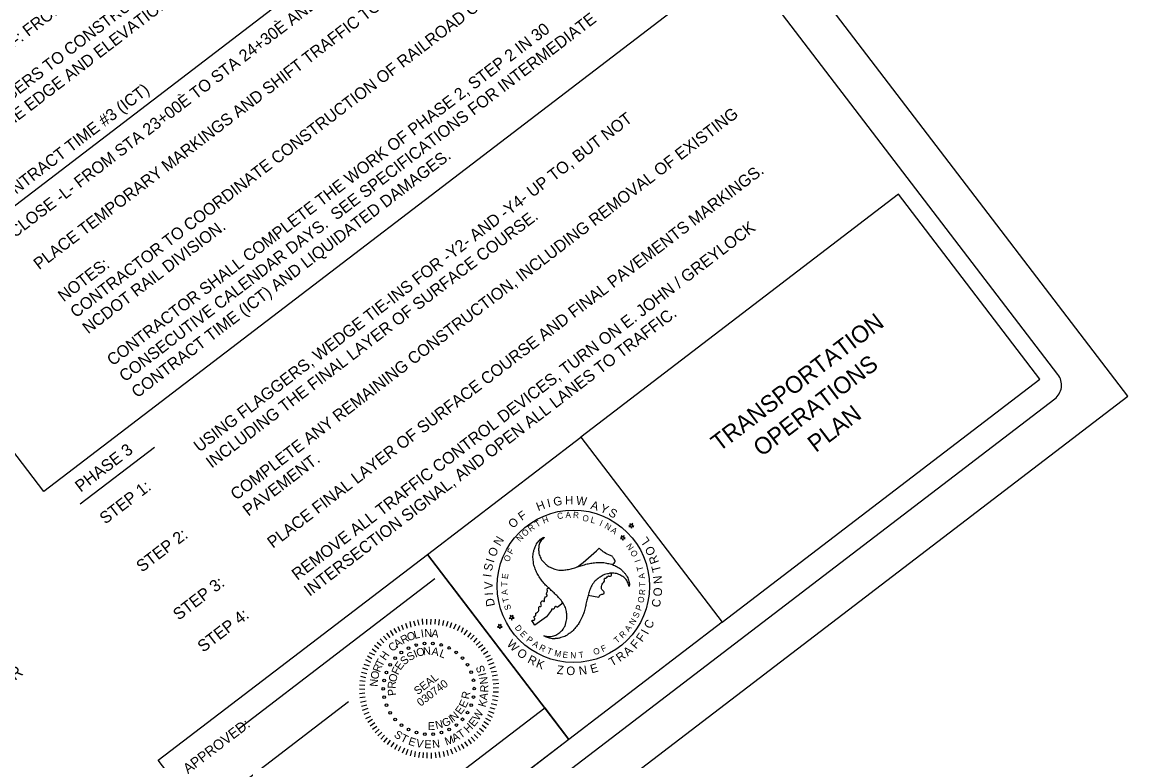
# Model space of a CAD drawing. Extents: x -606 to 2396, y -305 to 3662.
# Drawn here: x 1352 to 2005, y 861 to 1297 of the extents above; entities that cross this region are included whole.
import ezdxf

# ---------------------------------------------------------------- set-up
doc = ezdxf.new("R2010")
doc.units = 0
for name, color, linetype in [('DEV BORDER CELL', 7, 'Continuous'), ('DEV DOT SWIRL SEAL CELL', 7, 'Continuous'), ('Old_Level_9', 7, 'Continuous'), ('Sheet Plot Border Outside CELL', 7, 'Continuous'), ('Sheet Sticker Exception Certification CELL', 7, 'Continuous'), ('Text', 7, 'Continuous')]:
    doc.layers.add(name, color=color, linetype=linetype)

msp = doc.modelspace()

# ---------------------------------------------------------------- linework, layer by layer
at = {"layer": 'DEV BORDER CELL'}
for p, q in [((1963.25, 1088.61), (1337.94, 1906.36)), ((786.1, 175.54), (1961.32, 1074.19)), ((1479.25, 879.26), (1595.5, 968.15)), ((1605.31, 963.79), (1674.56, 873.24)), ((1481.07, 847.06), (1544.45, 895.53))]:
    msp.add_line(p, q, dxfattribs=at)
for points in [[(1869.07, 1195.06), (1681.6, 1051.71), (1765.12, 942.48), (1952.59, 1085.83)], [(1591.04, 982.46), (1681.6, 1051.71), (1765.12, 942.48), (1674.56, 873.23)], [(1432.13, 860.95), (1591.04, 982.46), (1674.56, 873.23), (1515.66, 751.72)]]:
    msp.add_lwpolyline(points, close=True, dxfattribs=at)
msp.add_arc((1955.08, 1082.36), 10.29, 307.40396, 37.40402, dxfattribs=at)
at = {"layer": 'DEV DOT SWIRL SEAL CELL'}
for p, q in [((1710.83, 999.54), (1709.97, 998.88)), ((1709.97, 998.88), (1711.06, 998.91)), ((1711.37, 999.96), (1710.48, 1000.53)), ((1710.48, 1000.53), (1710.83, 999.54)), ((1711.06, 998.91), (1711.44, 997.89)), ((1712.24, 1000.62), (1711.37, 999.96)), ((1711.44, 997.89), (1711.72, 998.91)), ((1711.72, 998.91), (1712.81, 998.94)), ((1711.92, 999.57), (1712.24, 1000.62)), ((1712.81, 998.94), (1711.92, 999.57)), ((1705.86, 992.42), (1705, 991.76)), ((1706.4, 992.83), (1705.51, 993.41)), ((1705.51, 993.41), (1705.86, 992.42)), ((1707.26, 993.49), (1706.4, 992.83)), ((1706.95, 992.44), (1707.26, 993.49)), ((1707.84, 991.81), (1706.95, 992.44)), ((1705, 991.76), (1706.09, 991.78)), ((1706.09, 991.78), (1706.47, 990.76)), ((1706.47, 990.76), (1706.75, 991.78)), ((1706.75, 991.78), (1707.84, 991.81)), ((1667.64, 951.35), (1671.01, 953.88)), ((1685.95, 958.28), (1692.21, 957.18)), ((1664.36, 949.55), (1661.4, 945.51)), ((1633.29, 940.07), (1632.43, 939.41)), ((1633.83, 940.48), (1632.93, 941.06)), ((1632.93, 941.06), (1633.29, 940.07)), ((1634.69, 941.14), (1633.83, 940.48)), ((1634.38, 940.1), (1634.69, 941.14)), ((1634.38, 940.1), (1634.69, 941.14)), ((1635.27, 939.46), (1634.38, 940.1)), ((1635.27, 939.46), (1634.38, 940.1)), ((1640.19, 945.33), (1639.33, 944.67)), ((1639.33, 944.67), (1640.42, 944.7)), ((1640.73, 945.75), (1639.84, 946.32)), ((1639.84, 946.32), (1640.19, 945.33)), ((1640.42, 944.7), (1640.8, 943.68)), ((1641.59, 946.4), (1640.73, 945.75)), ((1640.8, 943.68), (1641.08, 944.7)), ((1641.08, 944.7), (1642.17, 944.72)), ((1641.28, 945.36), (1641.59, 946.4)), ((1642.17, 944.72), (1641.28, 945.36)), ((1654.54, 940.66), (1653, 942.82)), ((1661.4, 945.51), (1654.54, 940.66)), ((1632.43, 939.41), (1633.52, 939.44)), ((1633.52, 939.44), (1633.9, 938.41)), ((1633.9, 938.41), (1634.18, 939.44)), ((1634.18, 939.44), (1635.27, 939.46)), ((1634.18, 939.44), (1635.27, 939.46))]:
    msp.add_line(p, q, dxfattribs=at)
for start, end in [(308.60748, 312.72752), (303.08246, 303.3802)]:
    msp.add_arc((1534.24, 1157.31), 233.19, start, end, dxfattribs=at)
for points in [[(1659.8, 934.46), (1662.41, 933.93), (1664.98, 934.14), (1667.36, 935.14), (1669.69, 936.73), (1671.57, 939), (1672.5, 940.93), (1672.74, 941.93), (1673.18, 943.65), (1673.32, 945.11), (1673.21, 948), (1672.54, 951), (1671.02, 953.86), (1670.88, 954.09), (1669.03, 956.46), (1666.87, 958.63), (1664.75, 960.69), (1662.48, 962.77), (1660.28, 964.87), (1658.45, 967.16), (1656.56, 969.94), (1655.2, 972.52), (1654.16, 975.43), (1653.71, 976.85), (1653.58, 978.17), (1653.36, 981.34), (1653.86, 984.43), (1654.37, 986.24), (1655.04, 987.7), (1655.16, 987.96), (1656.86, 990.41), (1659.01, 992.19), (1659.91, 992.57)], [(1659.92, 992.68), (1659.91, 992.57), (1658.15, 990.62), (1657.03, 988.24), (1656.71, 985.7), (1656.92, 982.92), (1657.96, 980.13), (1659.14, 978.37), (1659.91, 977.67), (1661.18, 976.41), (1662.35, 975.55), (1664.93, 974.24), (1667.85, 973.3), (1671.11, 973.19), (1671.38, 973.19), (1674.32, 973.58), (1677.32, 974.39), (1680.15, 975.2), (1683.07, 976.12), (1686.01, 976.95), (1688.91, 977.4), (1692.26, 977.67), (1695.15, 977.55), (1698.2, 977.01), (1699.67, 976.68), (1700.87, 976.12), (1703.74, 974.76), (1706.15, 972.75), (1707.49, 971.4), (1708.42, 970.09), (1708.59, 969.88), (1709.83, 967.15), (1710.28, 964.39), (1710.18, 963.46)], [(1700.13, 976.48), (1701.91, 978.23), (1701.01, 980), (1700.04, 981.32), (1698.08, 982.2), (1694.76, 984.04), (1692.46, 986.02)], [(1710.18, 963.46), (1709.36, 965.94), (1707.89, 968.09), (1705.82, 969.65), (1703.3, 970.87), (1700.39, 971.35), (1698.27, 971.21), (1697.27, 970.89), (1695.56, 970.47), (1694.2, 969.82), (1691.79, 968.29), (1689.5, 966.2), (1687.79, 963.44), (1687.66, 963.21), (1686.55, 960.43), (1685.73, 957.47), (1684.98, 954.6), (1684.34, 951.61), (1683.61, 948.62), (1682.54, 945.91), (1681.08, 942.87), (1679.53, 940.43), (1677.55, 938.07), (1676.52, 936.95), (1675.44, 936.19), (1672.85, 934.41), (1669.89, 933.29), (1668.08, 932.83), (1666.46, 932.7), (1666.18, 932.66), (1663.21, 932.92), (1660.61, 933.9), (1659.8, 934.46)], [(1692.21, 957.18), (1693.24, 958.62), (1694.69, 959.05), (1695.3, 959.37), (1695.49, 960.05), (1694.07, 961.63), (1693.85, 962.71), (1694.64, 965.45), (1695.57, 966.55), (1695.61, 968.22), (1695.97, 968.45), (1696.7, 968.56), (1697.68, 969.66), (1699.16, 969.62), (1699.67, 970.08), (1699.46, 971.25)], [(1653, 942.82), (1652.78, 942.97), (1652.97, 943.47), (1654.26, 943.82), (1654.43, 944.62), (1654.08, 945.03), (1654.16, 945.77), (1654.93, 946.15), (1654.96, 947.38), (1655.4, 947.96), (1656.59, 948.87), (1656.92, 951.37), (1657.44, 951.9), (1657.88, 951.64), (1658.29, 951.85), (1658.03, 953.5), (1658.07, 953.77), (1658.8, 955.05), (1659.26, 955.05), (1659.75, 954.6), (1659.97, 954.63), (1660.14, 955.15), (1660.16, 956.16), (1660.69, 957.32), (1661.83, 957.97), (1661.36, 958.96), (1661.95, 960.69), (1661.82, 961.38), (1661.51, 961.92)], [(1667.64, 951.35), (1666.98, 951.66), (1666.32, 951.4), (1665.87, 950.46), (1665.31, 950.06), (1664.36, 950.05), (1664.36, 949.55)]]:
    msp.add_spline(points, degree=3, dxfattribs=at)
at = {"layer": 'Old_Level_9'}
for p, q in [((1575.7, 940.95), (1576.83, 938.03)), ((1578.05, 941.8), (1579.17, 938.88)), ((1580.59, 942.79), (1581.22, 939.5)), ((1582.88, 943.29), (1583.73, 940.32)), ((1585.28, 943.86), (1585.91, 940.57)), ((1587.92, 944.31), (1588.1, 940.99)), ((1590.5, 944.24), (1590.53, 941.11)), ((1593, 944.26), (1592.93, 941.06)), ((1595.57, 944.18), (1595.35, 941.18)), ((1597.95, 943.96), (1597.61, 940.7)), ((1600.56, 943.43), (1599.88, 940.4)), ((1603.06, 942.83), (1602.04, 939.84)), ((1605.37, 942.08), (1604.35, 939.09)), ((1607.75, 941.22), (1606.55, 938.26)), ((1610.11, 940.19), (1608.56, 937.28)), ((1565.07, 934.07), (1567.19, 931.92)), ((1567, 935.87), (1568.97, 933.29)), ((1569.09, 937.46), (1570.76, 934.65)), ((1571.2, 938.61), (1572.82, 936.07)), ((1573.51, 939.9), (1574.84, 937.14)), ((1612.2, 939.11), (1610.92, 936.25)), ((1614.59, 937.64), (1612.61, 934.87)), ((1616.62, 936.21), (1614.67, 933.61)), ((1618.56, 934.7), (1616.46, 932.3)), ((1559.82, 928.8), (1562.41, 926.85)), ((1561.4, 930.64), (1563.72, 928.64)), ((1563.26, 932.53), (1565.28, 930.3)), ((1620.3, 933.04), (1618.3, 930.72)), ((1622.1, 931.11), (1619.74, 928.83)), ((1623.79, 929.1), (1621.31, 927.2)), ((1625.23, 927.21), (1622.75, 925.31)), ((1555.67, 922.49), (1558.31, 920.89)), ((1556.76, 924.57), (1559.77, 923.1)), ((1558.38, 926.76), (1560.9, 924.91)), ((1626.73, 925.05), (1624.19, 923.43)), ((1628.12, 922.81), (1625.36, 921.49)), ((1629.27, 920.7), (1626.26, 919.49)), ((1552.77, 915.38), (1555.77, 914.54)), ((1553.52, 917.69), (1556.68, 916.65)), ((1554.49, 920.33), (1557.51, 918.85)), ((1630.22, 918.43), (1627.2, 917.23)), ((1631.14, 915.99), (1627.87, 914.91)), ((1551.24, 907.92), (1554.31, 907.6)), ((1551.49, 910.47), (1554.52, 909.8)), ((1552.09, 912.98), (1555.27, 912.11)), ((1631.86, 913.4), (1628.77, 912.92)), ((1632.36, 911.1), (1629.34, 910.52)), ((1632.81, 908.46), (1629.56, 908.17)), ((1550.91, 905.47), (1554.09, 905.22)), ((1551.03, 903.04), (1554.13, 902.9)), ((1633.13, 906.18), (1629.78, 905.83)), ((1632.98, 901.03), (1629.88, 901.18)), ((1633.05, 903.61), (1629.91, 903.4)), ((1551.03, 900.37), (1554.2, 900.75)), ((1551.15, 897.94), (1554.32, 898.32)), ((1551.6, 895.3), (1554.9, 895.93)), ((1631.97, 893.5), (1628.69, 894.29)), ((1632.4, 896.03), (1629.44, 896.6)), ((1632.8, 898.38), (1629.57, 898.9)), ((1552.18, 892.9), (1555.32, 893.73)), ((1552.82, 890.41), (1556.01, 891.59)), ((1553.67, 888.07), (1556.68, 889.27)), ((1630.52, 888.61), (1627.36, 889.65)), ((1631.12, 891.11), (1628.11, 891.96)), ((1554.77, 885.6), (1557.63, 887)), ((1555.91, 883.49), (1558.62, 885.09)), ((1557.31, 881.25), (1559.97, 883.13)), ((1625.75, 879.61), (1623.33, 881.54)), ((1627.21, 881.83), (1624.32, 883.55)), ((1628.49, 884.06), (1625.57, 885.61)), ((1629.49, 886.25), (1626.65, 887.7)), ((1558.65, 879.29), (1561.29, 880.99)), ((1560.25, 877.2), (1562.58, 879.3)), ((1561.86, 875.29), (1564.22, 877.56)), ((1563.58, 873.46), (1565.76, 875.75)), ((1620.8, 873.94), (1618.68, 876.1)), ((1622.66, 875.83), (1620.27, 877.94)), ((1624.17, 877.77), (1621.75, 879.7)), ((1565.4, 871.7), (1567.43, 874.19)), ((1567.44, 870.27), (1569.36, 872.69)), ((1569.57, 868.91), (1571.43, 871.43)), ((1571.89, 867.54), (1573.31, 870.2)), ((1573.97, 866.45), (1575.32, 869.22)), ((1576.31, 865.25), (1577.68, 868.19)), ((1608.38, 865.7), (1607.06, 868.46)), ((1610.65, 866.65), (1609.25, 869.51)), ((1612.76, 867.79), (1611.24, 870.4)), ((1615, 869.19), (1613.12, 871.85)), ((1617.16, 870.68), (1615.26, 873.17)), ((1618.97, 872.22), (1616.8, 874.65)), ((1578.52, 864.42), (1579.71, 867.38)), ((1581.17, 863.62), (1581.95, 866.73)), ((1583.58, 862.94), (1584.1, 866.17)), ((1585.93, 862.54), (1586.53, 865.67)), ((1588.59, 862.37), (1588.73, 865.47)), ((1590.96, 862.14), (1590.96, 865.44)), ((1593.54, 862.06), (1593.43, 865.29)), ((1596.16, 862.34), (1595.78, 865.51)), ((1598.61, 862.63), (1598.05, 865.83)), ((1601.08, 863.11), (1600.5, 866.13)), ((1603.57, 863.76), (1602.74, 866.9)), ((1605.99, 864.5), (1604.96, 867.49))]:
    msp.add_line(p, q, dxfattribs=at)
for centre in [(1579.87, 927.15), (1584.49, 928.95), (1589.36, 929.87), (1594.32, 929.88), (1599.19, 928.98), (1603.82, 927.2), (1572, 921.18), (1575.66, 924.53), (1608.04, 924.6), (1611.71, 921.27), (1569.03, 917.22), (1614.7, 917.32), (1565.48, 908.01), (1566.83, 912.78), (1616.92, 912.89), (1618.29, 908.12), (1565.03, 903.07), (1618.75, 903.19), (1565.5, 898.14), (1616.96, 893.48), (1618.31, 898.25), (1566.87, 893.38), (1569.09, 888.94), (1614.76, 889.04), (1572.08, 884.99), (1575.75, 881.66), (1608.13, 881.73), (1611.78, 885.08), (1579.97, 879.06), (1584.6, 877.28), (1589.47, 876.38), (1594.43, 876.39), (1599.3, 877.31), (1603.92, 879.11)]:
    msp.add_circle(centre, 0.788, dxfattribs=at)
at = {"layer": 'Sheet Plot Border Outside CELL'}
msp.add_lwpolyline([(663.64, 50.42), (2004.54, 1075.77), (1336.37, 1949.58), (-4.54, 924.23)], close=True, dxfattribs=at)
at = {"layer": 'Sheet Sticker Exception Certification CELL'}
for p, q in [((1501.38, 770.39), (1660.29, 891.9)), ((1660.29, 891.89), (1674.57, 873.22)), ((1674.56, 873.23), (1515.66, 751.72))]:
    msp.add_line(p, q, dxfattribs=at)
at = {"layer": 'Text'}
msp.add_line((1386.09, 1012.22), (1429.97, 1045.78), dxfattribs=at)
msp.add_lwpolyline([(1276.8, 1134.37), (1681.63, 1443.93), (1769.46, 1329.08), (1364.63, 1019.52)], close=True, dxfattribs=at)
msp.add_circle((1677.2, 963.63), 44.97, dxfattribs=at)

# ---------------------------------------------------------------- texts
at = {"layer": 'DEV BORDER CELL'}
for s, height, rotation, p in [('TRANSPORTATION', 10, 37.34374, (1763.34, 1042.76)), ('OPERATIONS', 10, 37.34374, (1788.26, 1039.76)), ('PLAN', 10, 37.34374, (1820.35, 1042.23)), ('APPROVED:  ', 6, 37.40396, (1449.74, 852.69))]:
    msp.add_text(s, height=height, rotation=rotation, dxfattribs=at).set_placement(p)
at = {"layer": 'DEV DOT SWIRL SEAL CELL'}
for s, height, rotation, p in [('H', 5.04, 20.85795, (1656.46, 1007.94)), ('I', 5.04, 13.208, (1662.36, 1010.09)), ('G', 5.04, 8.92066, (1665.77, 1010.95)), ('H', 5.04, 0.8672, (1672.31, 1011.87)), ('W', 5.04, 353.21724, (1678.59, 1011.88)), ('A', 5.04, 344.18021, (1687.02, 1009.39)), ('Y', 5.04, 337.15234, (1692.55, 1007.77)), ('F', 5.04, 34.66149, (1646.75, 1002.14)), ('C', 3.63, 10.88002, (1668.02, 1003.13)), ('A', 3.63, 0.72385, (1672.57, 1003.93)), ('R', 3.63, 355.64577, (1676.89, 1004.03)), ('O', 3.63, 350.56768, (1682.31, 1002.23)), ('S', 5.04, 330.62886, (1697.48, 1005.68)), ('O', 5.04, 43.16891, (1641.57, 997.47)), ('R', 3.63, 36.27045, (1651.97, 995.62)), ('H', 3.63, 21.03619, (1659.71, 1000.45)), ('L', 3.63, 345.4896, (1687.09, 1001.27)), ('I', 3.63, 335.33343, (1692.25, 999.54)), ('N', 3.63, 330.25535, (1695.22, 998.15)), ('N', 5.04, 58.99002, (1633.98, 986.98)), ('N', 3.63, 46.42661, (1645.73, 989.6)), ('O', 3.63, 41.34853, (1648.59, 992.68)), ('A', 3.63, 325.17726, (1698.95, 995.9)), ('O', 5.04, 67.49744, (1631.18, 980.59)), ('F', 3.63, 61.66087, (1641.09, 982.13)), ('N', 3.63, 125.13693, (1713.13, 986.5)), ('I', 5.04, 71.78478, (1630.13, 977.23)), ('O', 3.63, 66.73895, (1639.17, 977.7)), ('O', 3.63, 120.33085, (1715.59, 982.25)), ('I', 3.63, 110.17468, (1717.02, 978.61)), ('S', 5.04, 77.98881, (1629.07, 972.25)), ('T', 3.63, 105.0966, (1718.7, 973.11)), ('I', 5.04, 82.27614, (1628.65, 968.75)), ('V', 5.04, 88.98456, (1629.62, 961.82)), ('T', 3.63, 87.05129, (1638.21, 963.37)), ('E', 3.63, 81.97321, (1638.47, 967.74)), ('A', 3.63, 100.01851, (1719.57, 968.31)), ('T', 3.63, 89.86234, (1719.74, 963.23)), ('I', 5.04, 93.2719, (1629.88, 958.31)), ('A', 3.63, 97.20746, (1638.6, 958.65)), ('R', 3.63, 84.78426, (1719.43, 958.28)), ('D', 5.04, 100.86301, (1630.97, 952.18)), ('T', 3.63, 102.28555, (1639.36, 954.47)), ('O', 3.63, 79.70617, (1718.61, 953.55)), ('S', 3.63, 107.36363, (1640.62, 950.21)), ('S', 3.63, 64.47192, (1715.21, 944.49)), ('P', 3.63, 69.55, (1717.09, 948.83)), ('D', 3.63, 307.67597, (1642.36, 939.13)), ('A', 3.63, 54.31575, (1710.05, 936.44)), ('N', 3.63, 59.39383, (1712.84, 940.32)), ('E', 3.63, 312.75406, (1645.4, 935.34)), ('P', 3.63, 322.91023, (1649.05, 931.57)), ('T', 3.63, 39.0815, (1702.92, 929.71)), ('R', 3.63, 44.15958, (1706.34, 932.63)), ('A', 3.63, 327.98831, (1652.71, 928.76)), ('R', 3.63, 333.0664, (1656.67, 926.33)), ('T', 3.63, 338.14448, (1661.16, 924.22)), ('O', 3.63, 18.76916, (1689.63, 922.92)), ('F', 3.63, 23.84724, (1694.44, 924.73)), ('M', 3.63, 348.30065, (1665.72, 922.56)), ('E', 3.63, 353.37873, (1670.69, 921.55)), ('N', 3.63, 358.45682, (1675.33, 921.12)), ('T', 3.63, 8.61299, (1680.67, 921.12))]:
    msp.add_text(s, height=height, rotation=rotation, dxfattribs=at).set_placement(p)
at = {"layer": 'Old_Level_9'}
for s, height, rotation, p in [('R', 4.72, 27.42552, (1576.66, 929.41)), ('O', 4.72, 20.49076, (1579.92, 931.11)), ('L', 4.72, 13.14987, (1583.58, 932.5)), ('I', 4.72, 8.20992, (1587.53, 933.31)), ('N', 4.72, 2.3078, (1589.35, 933.6)), ('A', 4.72, 354.40904, (1593.27, 933.61)), ('C', 4.72, 42.34388, (1570.5, 924.7)), ('A', 4.72, 35.37883, (1573.23, 927.1)), ('O', 4.7, 15.27885, (1585.21, 921.94)), ('N', 4.7, 4.79698, (1588.72, 922.89)), ('A', 4.7, 351.34774, (1593.3, 923.09)), ('T', 4.72, 62.83975, (1564.31, 915.72)), ('H', 4.72, 55.14731, (1566.33, 919.46)), ('S', 4.7, 41.87199, (1577.48, 916.81)), ('S', 4.7, 30.44542, (1580.58, 919.34)), ('I', 4.7, 22.88603, (1584.06, 921.38)), ('L', 4.7, 338.93627, (1597.73, 922.23)), ('R', 4.72, 69.57941, (1562.99, 912.5)), ('F', 4.7, 63.80392, (1573.76, 910.98)), ('E', 4.7, 53.9929, (1575.11, 913.74)), ('S', 4.72, 109.66185, (1625.33, 913.46)), ('N', 4.72, 85.47062, (1561.62, 904.22)), ('O', 4.72, 77.34818, (1561.91, 908.37)), ('R', 4.7, 87.15176, (1572.26, 903.07)), ('O', 4.7, 75.65578, (1572.47, 906.69)), ('SEAL', 4.699, 37.40396, (1585.32, 899.27)), ('030740', 4.699, 37.40396, (1587.06, 892.47)), ('I', 4.72, 103.45036, (1625.92, 911.25)), ('N', 4.72, 96.77653, (1626.89, 906.01)), ('P', 4.7, 97.52761, (1572.64, 899.27)), ('R', 4.7, 77.75323, (1615.54, 896.67)), ('R', 4.72, 88.55428, (1626.91, 900.92)), ('E', 4.7, 64.56078, (1613.59, 891.4)), ('K', 4.72, 73.54497, (1625.31, 891.92)), ('A', 4.72, 80.92565, (1626.2, 896.18)), ('N', 4.7, 40.53176, (1606.66, 883.59)), ('E', 4.7, 53.20965, (1610.75, 887.5)), ('W', 4.72, 59.40972, (1621.3, 883.89)), ('E', 4.7, 2.27315, (1591.38, 878.67)), ('N', 4.7, 13.46232, (1596.28, 879.26)), ('G', 4.7, 24.88521, (1600.97, 880.33)), ('I', 4.7, 33.02855, (1605.47, 882.67)), ('H', 4.72, 43.41518, (1615.12, 876.74)), ('E', 4.72, 51.56872, (1618.6, 880.31)), ('S', 4.72, 325.61597, (1570.88, 875.13)), ('T', 4.72, 333.02835, (1574.73, 872.54)), ('M', 4.72, 19.741, (1602.26, 869.58)), ('A', 4.72, 27.58613, (1606.91, 871.51)), ('T', 4.72, 34.79055, (1610.72, 873.55)), ('E', 4.72, 341.22646, (1579.38, 870.31)), ('V', 4.72, 349.33376, (1584.04, 868.87)), ('E', 4.72, 357.63521, (1589.17, 868.11)), ('N', 4.72, 5.73296, (1594.12, 868.08))]:
    msp.add_text(s, height=height, rotation=rotation, dxfattribs=at).set_placement(p)
at = {"layer": 'Text'}
for s, height, rotation, p in [('PROPOSED -Y2-: FROM STA 13+00È TO STA 15+30È', 7, 37.40396, (1264.16, 1277.9)), ('USE FLAGGERS TO CONSTRUCT TEMPORARY TIE-INS FOR -Y2- AND -Y4-, ', 7, 37.40396, (1307.53, 1221.18)), ('PROPOSED -Y3-: FROM STA 10+75È TO STA 12+68È', 7, 37.40396, (1278.62, 1258.99)), ('CLOSE -L- FROM STA 23+00È TO STA 24+30È AND CONSTRUCT RAIL CROSSING.', 7, 37.40396, (1347.43, 1169)), ('PROPOSED -Y4-: FROM STA 10+45È TO STA 12+00È', 7, 37.40396, (1293.07, 1240.08)), ('UP TO THE EDGE AND ELEVATION OF EXISTING PAVEMENT.', 7, 37.40396, (1314.76, 1211.73)), ('PLACE TEMPORARY MARKINGS AND SHIFT TRAFFIC TO PHASE 3 PATTERN.', 7, 37.40396, (1361.89, 1150.09)), ('CONTRACTOR TO COORDINATE CONSTRUCTION OF RAILROAD CROSSING WITH ', 7, 37.40396, (1383.58, 1121.73)), ('CONSECUTIVE CALENDAR DAYS.  SEE SPECIFICATIONS FOR INTERMEDIATE ', 7, 37.40396, (1412.49, 1083.92)), ('CONTRACTOR SHALL COMPLETE THE WORK OF PHASE 2, STEP 2 IN 30 ', 7, 37.40396, (1405.26, 1093.37)), ('INTERMEDIATE CONTRACT TIME #3 (ICT)', 7, 37.40396, (1279.75, 1142.28)), ('USING FLAGGERS, WEDGE TIE-INS FOR -Y2- AND -Y4- UP TO, BUT NOT ', 7, 37.40396, (1456.48, 1042.46)), ('COMPLETE ANY REMAINING CONSTRUCTION, INCLUDING REMOVAL OF EXISTING ', 7, 37.40396, (1478.17, 1014.1)), ('CONTRACT TIME (ICT) AND LIQUIDATED DAMAGES.', 7, 37.40396, (1419.72, 1074.47)), ('PLACE FINAL LAYER OF SURFACE COURSE AND FINAL PAVEMENTS MARKINGS.', 7, 37.40396, (1499.85, 985.74)), ('INCLUDING THE FINAL LAYER OF SURFACE COURSE.', 7, 37.40396, (1463.71, 1033)), ('NCDOT RAIL DIVISION.', 7, 37.40396, (1390.8, 1112.28)), ('REMOVE ALL TRAFFIC CONTROL DEVICES, TURN ON E. JOHN / GREYLOCK ', 7, 37.40396, (1514.31, 966.83)), ('NOTES: ', 7, 37.40396, (1376.35, 1131.18)), ('INTERSECTION SIGNAL, AND OPEN ALL LANES TO TRAFFIC.', 7, 37.40396, (1521.54, 957.38)), ('PHASE 3', 7, 37.40396, (1386.42, 1018.84)), ('PAVEMENT.', 7, 37.40396, (1485.4, 1004.65)), ('STEP 1:', 7, 37.40396, (1400.88, 999.94)), ('T', 3.63, 31.19236, (1655.79, 998.26)), ('STEP 2:', 7, 37.40396, (1422.56, 971.58)), ('L', 5.04, 124.83296, (1722.58, 990.21)), ('O', 5.04, 116.39361, (1725.99, 983.26)), ('R', 5.04, 110.15583, (1727.83, 977.84)), ('T', 5.04, 104.28498, (1729.02, 972.59)), ('STEP 3:', 7, 37.40396, (1444.25, 943.22)), ('N', 5.04, 96.29595, (1729.76, 965.3)), ('O', 5.04, 87.8566, (1729.44, 957.57)), ('C', 5.04, 80.48468, (1728.23, 950.91)), ('STEP 4:', 7, 37.40396, (1458.7, 924.31)), ('C', 5.04, 65.40726, (1723.17, 938.08)), ('F', 5.04, 55.16663, (1717.89, 930.31)), ('I', 5.04, 61.15423, (1721.14, 934.74)), ('W', 5.04, 315.55395, (1637.55, 929.07)), ('A', 5.04, 42.20739, (1709.38, 922.03)), ('F', 5.04, 49.17903, (1714.19, 926.25)), ('O', 5.04, 324.51867, (1643.42, 923.31)), ('R', 5.04, 332.95802, (1649.7, 918.79)), ('K', 5.04, 339.1958, (1654.74, 916.07)), ('T', 5.04, 30.09876, (1699.94, 916.21)), ('R', 5.04, 35.96961, (1704.67, 918.78)), ('THE FOLLOWING LISTED WORK ZONE STRATEGIES ARE RECOMMENDED FOR  ', 7, 37.40396, (1069.1, 694.78)), ('Z', 5.04, 353.57272, (1667.25, 911.98)), ('O', 5.04, 359.92725, (1673.03, 911.2)), ('N', 5.04, 8.3666, (1680.77, 911.15)), ('E', 5.04, 16.35563, (1688.03, 912.16))]:
    msp.add_text(s, height=height, rotation=rotation, dxfattribs=at).set_placement(p)

doc.saveas('drawing.dxf')
